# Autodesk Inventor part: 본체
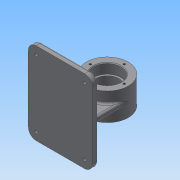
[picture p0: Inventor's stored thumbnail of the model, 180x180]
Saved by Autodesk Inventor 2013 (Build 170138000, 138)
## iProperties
Created: 2019-09
Part Number: 본체
Material: 일반
Document SubType Name: Modeling
Designer: Administrator
Density: 1 g/cm^3
Author: Administrator
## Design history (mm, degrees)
sketch "스케치1"
  geometry: C1 r 32 at (0, 0); 1 further point
  constraints: 1 centre point, 1 coincident
  dimensions: "d0" = 64 diameter of C1
extrude "돌출1" new body sketch "스케치1" distance "d1" = 21; taper "d2" = 0 deg
hole "구멍1" diameter "d5" = 36; stored, may be unused: countersink angle "d9" = 90 deg, drill point angle "d11" = 118 deg; dims "d3" = 10, "d4" = 10, "d6" = 6, "d7" = 42, "d8" = 15, "d10" = 8
sketch "스케치2"
  geometry: C1 r 21 at (0, 0) reference; 1 further point
  constraints: 1 vertical alignment
  dimensions: "d12" = 26 distance of C1.centre point (0, 26)
hole "구멍2" sketch "스케치2" at (0, 26) diameter "d13" = 3.242; stored, may be unused: countersink angle "d17" = 90 deg, drill point angle "d19" = 118 deg; dims "d14" = 8, "d15" = 42, "d16" = 15, "d18" = 10
fillet "모깎기1" dims "d23" = 0.3
chamfer "모따기1" distance "d24" = 1; stored, may be unused: second distance "d25" = 2, angle "d26" = 45 deg
node "작업 평면1"
sketch "스케치3"
  geometry: L1 (62, 63)-(-36, 63); L2 (-36, 63)-(-36, -63); L3 (-36, -63)-(62, -63); L4 (62, -63)-(62, 63); 1 further point
  constraints: 8 end point, 2 parallel, 1 horizontal, 1 perpendicular
  dimensions: "d28" = 98 distance of L3.end L2.end; "d29" = 126 distance of L2.end L1.end; "d30" = 63 distance from line of point (0, 0) L3; "d31" = 62 distance from line of point (0, 0) L4
extrude "돌출2" join sketch "스케치3" distance "d32" = 9; taper "d33" = 0 deg
fillet "모깎기2" dims "d34" = 12
sketch "스케치4"
  geometry: A1 r 12 centre (-50, -51) between (-62, -51) and (-50, -63) reference; A2 r 12 centre (24, -51) between (24, -63) and (36, -51) reference; A3 r 12 centre (24, 51) between (36, 51) and (24, 63) reference; A4 r 12 centre (-50, 51) between (-50, 63) and (-62, 51) reference; 5 further points
  constraints: 4 coincident
hole "구멍3" sketch "스케치4" at (-50, 51), (24, 51), (24, -51), (-50, -51) diameter "d35" = 4.5; stored, may be unused: countersink angle "d39" = 90 deg, drill point angle "d41" = 0 deg; dims "d36" = 8, "d37" = 8, "d38" = 4.4, "d40" = 10
sketch "스케치5"
  geometry: L1 (-4, -17)-(4, -17); L2 (4, -17)-(4, 17); L3 (4, 17)-(-4, 17); L4 (-4, 17)-(-4, -17); 3 further points
  constraints: 8 end point, 2 midpoint, 2 parallel, 1 horizontal, 1 horizontal alignment, 1 perpendicular, 1 vertical alignment
  dimensions: "d45" = 8 distance of L2.end L3.end; "d47" = 34 distance of L3.end L1.start
extrude "돌출3" join sketch "스케치5" stored distance "d48" = 10; taper "d49" = 0 deg
sketch "스케치6"
  geometry: L1 (-32, -48.033)-(-32, -30.644); C1 r 32 at (0, 0) reference; 1 further point
  constraints: 2 end point, 1 tangent, 1 vertical
feature "리브1" sketch "스케치6" dims "d50" = 1, "d51" = 8, "d52" = 0, "d53" = 0, "d54" = 1, "d55" = 1
sketch "스케치7"
  geometry: L1 (-62, 51)-(-62, -51) reference; 2 further points
  constraints: 1 horizontal alignment, 1 other
  dimensions: "d56" = 10 distance from line of point (-52, 0) L1
feature "엠보싱1" sketch "스케치7" dims "d20" = 40, "d57" = 0.5, "d58" = 0
fillet "모깎기3" dims "d59" = 3
fillet "모깎기4" dims "d60" = 3
fillet "모깎기5" dims "d61" = 3
fillet "모깎기6" dims "d62" = 3
node "솔리드1"
pattern_circular "원형 패턴1" dims angle "d21" = 360 deg
mirror "대칭1"
mirror "대칭2"
other parameters: "d27" = -59
